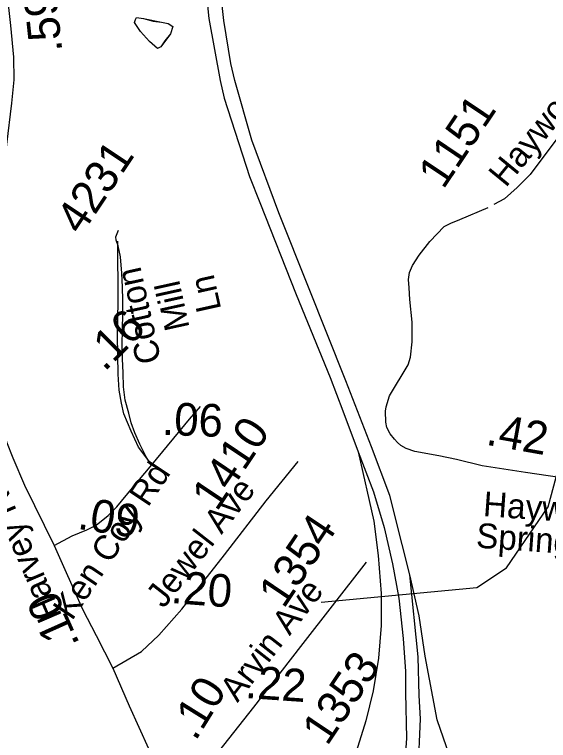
# Model space of a CAD drawing. Extents: x 1715610 to 1720914, y 798298 to 802505.
# Drawn here: x 1715888.3 to 1715932.8, y 799772 to 799832.4 of the extents above; entities that cross this region are included whole.
import ezdxf

# ---------------------------------------------------------------- set-up
doc = ezdxf.new("R2010")
doc.units = 0
doc.layers.add('Default', color=7, linetype='Continuous')

msp = doc.modelspace()

# ---------------------------------------------------------------- linework, layer by layer
at = {"layer": 'Default'}
for points in [[(1715913.865, 799783.456), (1715926.835, 799784.693), (1715929.284, 799786.328), (1715932.753, 799791.412), (1715933.821, 799795.307), (1715934.494, 799803.62), (1715936.271, 799807.905), (1715940.869, 799813.983), (1715944.236, 799828.141), (1715944.399, 799831.987), (1715940.311, 799845.322), (1715939.674, 799850.143), (1715940.195, 799853.75), (1715941.312, 799854.725), (1715943.603, 799854.265), (1715956.425, 799858.901), (1715957.776, 799859.961), (1715959.574, 799863.781), (1715959.922, 799867.267), (1715958.277, 799874.754), (1715959.996, 799882.819), (1715961.653, 799887.001)], [(1715907.475, 799873.677), (1715907.219, 799871.214), (1715905.901, 799860.999), (1715904.633, 799850.758), (1715904.042, 799844.761), (1715903.862, 799841.409), (1715903.955, 799837.337), (1715904.479, 799832.054), (1715905.428, 799826.893), (1715905.762, 799825.42), (1715907.867, 799818.914), (1715908.732, 799816.741), (1715911.761, 799809.075), (1715914.608, 799802.168), (1715915.662, 799799.405), (1715916.931, 799795.971)], [(1715922.018, 799775.69), (1715921.924, 799778.916), (1715921.227, 799785.75), (1715920.596, 799788.26), (1715919.573, 799792.351), (1715918.055, 799796.39), (1715915.899, 799801.894), (1715912.799, 799809.701), (1715910.314, 799815.89), (1715908.081, 799821.916), (1715906.648, 799826.886), (1715906.329, 799828.312), (1715905.74, 799831.882), (1715905.135, 799837.47), (1715905.006, 799841.013), (1715905.147, 799844.055), (1715905.586, 799849.399), (1715907.053, 799862.114), (1715908.288, 799870.155), (1715908.697, 799873.648)], [(1715887.585, 799834.985), (1715887.96, 799831.478), (1715888.231, 799828.832), (1715888.24, 799826.949), (1715888.059, 799825.001), (1715887.645, 799821.58), (1715887.043, 799817.108), (1715887.035, 799814.677), (1715886.966, 799811.853), (1715886.98, 799808.164), (1715887.054, 799806.818), (1715887.014, 799803.184), (1715887.069, 799801.068), (1715887.121, 799799.414), (1715887.192, 799798.806), (1715887.621, 799796.808), (1715888.149, 799795.48), (1715889.133, 799793.201), (1715891.599, 799788.185)], [(1715901.493, 799831.381), (1715901.293, 799830.779), (1715900.84, 799830.192), (1715900.498, 799829.691), (1715900.207, 799829.574), (1715899.537, 799830.136), (1715898.787, 799830.965), (1715898.3, 799831.72), (1715898.376, 799831.986), (1715898.474, 799832.13), (1715899.052, 799832.049), (1715899.846, 799831.823), (1715900.544, 799831.763), (1715901.098, 799831.65), (1715901.493, 799831.381)], [(1715901.493, 799831.381), (1715901.293, 799830.779), (1715900.498, 799829.691), (1715900.207, 799829.574), (1715899.537, 799830.136), (1715898.787, 799830.965), (1715898.3, 799831.72), (1715898.376, 799831.986), (1715898.474, 799832.13), (1715899.052, 799832.049), (1715900.544, 799831.763), (1715901.098, 799831.65), (1715901.493, 799831.381)], [(1715939.996, 799825.319), (1715938.317, 799827.019), (1715937.804, 799827.218), (1715937.207, 799827.186), (1715936.872, 799826.9), (1715934.066, 799822.823), (1715931.265, 799819.078), (1715930.184, 799817.995), (1715929.118, 799817.053), (1715928.229, 799816.582)], [(1715934.449, 799793.742), (1715932.777, 799793.98), (1715930.864, 799794.25), (1715927.261, 799794.822), (1715925.116, 799795.331), (1715923.644, 799795.638), (1715921.668, 799796.009), (1715920.92, 799796.26), (1715920.476, 799796.503), (1715920.2, 799796.748), (1715919.965, 799797.036), (1715919.598, 799797.484), (1715919.319, 799798.009), (1715919.23, 799798.462), (1715919.2, 799799.377), (1715919.257, 799799.737), (1715919.556, 799800.641), (1715921.092, 799803.217), (1715921.299, 799803.864), (1715921.435, 799805.152), (1715921.447, 799806.786), (1715921.233, 799808.654), (1715921.18, 799809.641), (1715921.116, 799810.326), (1715921.213, 799810.916), (1715921.466, 799811.507), (1715922.022, 799812.355), (1715922.898, 799813.505), (1715924.107, 799814.742), (1715924.642, 799815.026), (1715925.416, 799815.329), (1715927.776, 799816.331)], [(1715899.658, 799794.916), (1715899.271, 799795.58), (1715898.747, 799796.634), (1715898.324, 799797.562), (1715898.029, 799798.397), (1715897.813, 799799.21), (1715897.524, 799800.276), (1715897.392, 799801.385), (1715897.355, 799802.552), (1715897.309, 799803.724), (1715897.28, 799804.888), (1715897.302, 799806.167), (1715897.322, 799807.458), (1715897.316, 799808.617), (1715897.29, 799809.698), (1715897.244, 799810.87), (1715897.14, 799812.223), (1715896.947, 799813.127), (1715896.771, 799813.591), (1715896.731, 799813.893), (1715896.975, 799814.43)], [(1715899.731, 799794.909), (1715898.636, 799796.362), (1715898.015, 799797.715), (1715897.411, 799799.15), (1715897.214, 799800.036), (1715897.021, 799801.122), (1715896.947, 799802.441), (1715896.876, 799805.634), (1715896.949, 799808.491), (1715896.899, 799813.529)], [(1715899.731, 799794.909), (1715902.872, 799798.705), (1715903.785, 799799.768)], [(1715916.931, 799795.971), (1715918.231, 799790.214), (1715918.601, 799787.359), (1715918.855, 799784.198), (1715918.85, 799781.536), (1715918.62, 799778.802), (1715918.185, 799776.072), (1715917.579, 799773.575), (1715916.755, 799771.017), (1715915.322, 799767.326), (1715914.615, 799765.296), (1715914.045, 799763.338), (1715913.673, 799761.455), (1715913.548, 799760.472), (1715913.653, 799758.062)], [(1715916.931, 799795.971), (1715918.218, 799792.643), (1715919.104, 799789.694), (1715919.808, 799786.664), (1715920.315, 799783.813), (1715920.689, 799780.429), (1715920.872, 799777.682), (1715920.888, 799775.907), (1715920.949, 799772.149), (1715920.747, 799768.98), (1715920.454, 799766.229), (1715919.623, 799759.945)], [(1715891.599, 799788.185), (1715893.108, 799788.984), (1715894.341, 799789.477), (1715895.109, 799789.883), (1715896.098, 799790.674), (1715896.838, 799791.394), (1715898.133, 799792.987), (1715899.731, 799794.909)], [(1715896.498, 799777.978), (1715898.886, 799779.37), (1715900.32, 799780.711), (1715902.233, 799782.882), (1715905.794, 799787.401), (1715909.266, 799791.902), (1715911.924, 799795.185)], [(1715891.599, 799788.185), (1715893.964, 799782.895), (1715895.105, 799780.681), (1715896.498, 799777.978)], [(1715901.218, 799767.705), (1715902.563, 799768.366), (1715903.142, 799768.759), (1715903.705, 799769.28), (1715905.315, 799771.027), (1715908.232, 799774.726), (1715912.149, 799779.787), (1715917.636, 799786.799)], [(1715928.127, 799762.517), (1715925.502, 799767.976), (1715924.286, 799771.426), (1715923.505, 799773.667), (1715922.518, 799778.962), (1715922.026, 799782.342), (1715921.227, 799785.75)], [(1715896.498, 799777.978), (1715897.86, 799774.844), (1715899.478, 799771.274), (1715901.218, 799767.705)], [(1715920.77, 799760.288), (1715921.448, 799764.84), (1715921.947, 799769.304), (1715922.133, 799773.741), (1715922.018, 799775.69)]]:
    msp.add_lwpolyline(points, dxfattribs=at)

# ---------------------------------------------------------------- texts
for s, height, rotation, p in [('Hayworth Springs Rd', 2.06625, 50.67435, (1715929.236, 799817.92)), ('.59', 2.7188, 96.10601, (1715892.291, 799829.333)), ('1151', 2.7188, 56.20506, (1715924.029, 799817.762)), ('4231', 2.7188, 56.20506, (1715893.862, 799813.948)), ('Cotton', 2.0663, 102.4636, (1715900.533, 799803.551)), (' Ln', 2.0663, 102.4636, (1715905.703, 799807.111)), (' Mill', 2.0663, 102.4636, (1715903.064, 799805.577)), ('.16', 2.7188, 44.98557, (1715895.802, 799802.612)), ('.06', 2.7188, 357.97051, (1715900.564, 799797.396)), ('1410', 2.7188, 56.20506, (1715905.163, 799790.946)), ('.42', 2.7188, 349.88264, (1715927.509, 799796.59)), ('Ken Coy Rd', 2.0663, 56.20506, (1715893.09, 799781.863)), ('Harvey Rd', 2.0663, 113.34384, (1715892.29, 799782.331)), ('Jewel Ave', 2.0663, 52.04496, (1715900.729, 799782.878)), ('Hayworth ', 2.0663, 355.96648, (1715927.299, 799790.633)), ('.09', 2.7188, 351.09733, (1715893.479, 799789.581)), ('1354', 2.7188, 56.20506, (1715910.731, 799782.854)), ('Springs Rd', 2.0663, 355.96648, (1715926.715, 799788.014)), ('.20', 2.7188, 355.55568, (1715901.28, 799783.403)), ('Arvin Ave', 2.0663, 52.06852, (1715906.88, 799775.051)), ('.10', 2.7188, 114.08327, (1715893.775, 799779.987)), ('1353', 2.7188, 56.20506, (1715914.353, 799771.43)), ('.22', 2.7188, 356.05744, (1715907.473, 799775.494)), ('.10', 2.7188, 58.17317, (1715903.382, 799771.838))]:
    msp.add_text(s, height=height, rotation=rotation, dxfattribs=at).set_placement(p)

doc.saveas('drawing.dxf')
